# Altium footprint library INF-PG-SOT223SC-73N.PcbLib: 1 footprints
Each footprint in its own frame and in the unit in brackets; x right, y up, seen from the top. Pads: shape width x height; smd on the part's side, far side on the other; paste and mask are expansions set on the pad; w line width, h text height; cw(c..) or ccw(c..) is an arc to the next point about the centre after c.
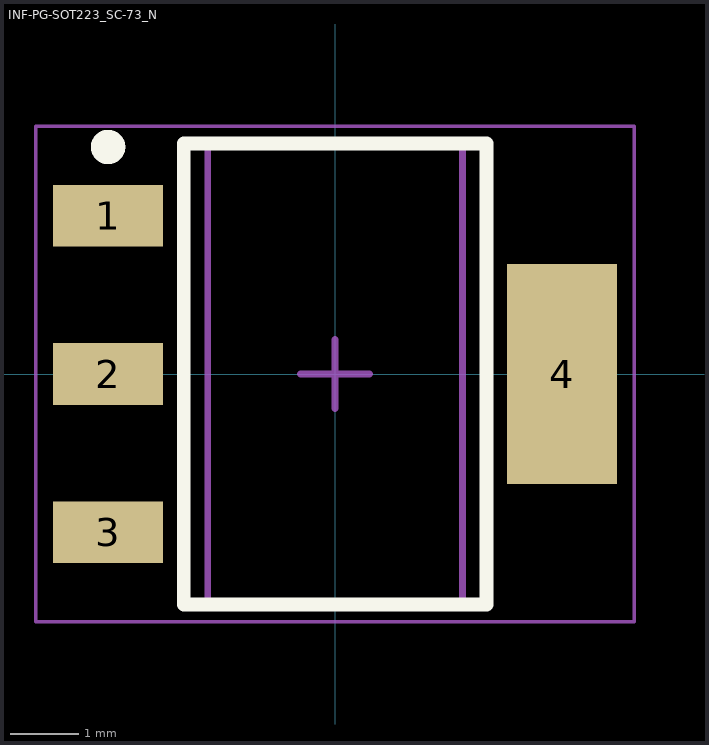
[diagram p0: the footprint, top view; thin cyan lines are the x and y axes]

## INF-PG-SOT223_SC-73_N [mm] "SOT223, 4-Leads, Body 6.5x3.5mm, Pitch 2.3mm, IPC Medium Density"
height 1.8
pads (4):
  rect 1.6x0.9 smd: 1(-3.3,2.3) 2(-3.3,0) 3(-3.3,-2.3)
  rect 1.6x3.2 smd: 4(3.3,0)
Top Overlay:
  circle w0.25: c-3.3,3.3 r0.125
  lines w0.2: -2.2,-3.35 -2.2,3.35 2.2,3.35 2.2,-3.35 -2.2,-3.35
Mechanical 13:
  lines w0.1: -1.85,-3.35 -1.85,3.35 1.85,3.35 1.85,-3.35 -1.85,-3.35
Mechanical 15:
  lines w0.05: -4.35,-3.6 -4.35,3.6 4.35,3.6 4.35,-3.6 -4.35,-3.6
  lines w0.1: -0.5,0 0.5,0 ; 0,-0.5 0,0.5
3D body: height 1.8, standoff 0.1, extent -1.85,-3.35 1.85,3.35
